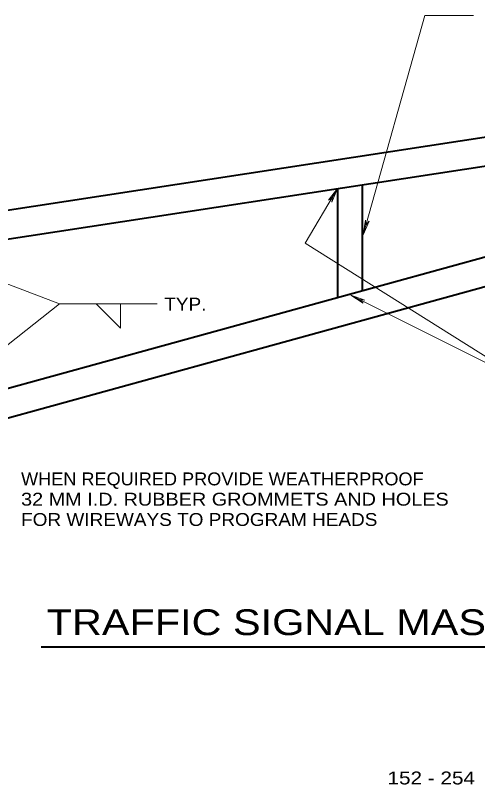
# Model space of a CAD drawing. Extents: x 312583 to 312854, y 144419 to 144597.
# Drawn here: x 312762.98 to 312790.22, y 144520.85 to 144566.2 of the extents above; entities that cross this region are included whole.
import ezdxf

# ---------------------------------------------------------------- set-up
doc = ezdxf.new("R2010")
doc.units = 0
doc.header["$LTSCALE"] = 0.3
doc.layers.add('1', color=7, linetype='Continuous', lineweight=13)

msp = doc.modelspace()

# ---------------------------------------------------------------- linework, layer by layer
at = {"layer": '1'}
for p, q in [((312783.4824, 144553.2632), (312787.101, 144566.2046)), ((312787.101, 144566.2046), (312789.976, 144566.2046)), ((312781.9644, 144556.0002), (312781.4354, 144555.3102)), ((312781.9644, 144556.0002), (312781.6194, 144555.1952)), ((312781.4354, 144555.3102), (312781.6654, 144555.4866)), ((312781.6194, 144555.1952), (312781.6654, 144555.4866)), ((312783.4824, 144553.2632), (312783.6127, 144554.1296)), ((312783.6127, 144554.1296), (312783.6357, 144553.8306)), ((312783.4824, 144553.2632), (312783.8197, 144554.0682)), ((312783.8197, 144554.0682), (312783.6357, 144553.8306)), ((312782.7464, 144549.7136), (312783.4747, 144549.2306)), ((312782.7464, 144549.7136), (312783.5667, 144549.4222)), ((312771.3307, 144549.1999), (312765.573, 144549.1999)), ((312783.4747, 144549.2306), (312783.2754, 144549.4529)), ((312783.5667, 144549.4222), (312783.2754, 144549.4529))]:
    msp.add_line(p, q, dxfattribs=at)
at = {"layer": '1', "lineweight": 40}
for p, q in [((312730.935, 144549.8976), (312834.251, 144565.6909)), ((312730.935, 144548.1956), (312834.504, 144564.0272)), ((312730.935, 144535.5226), (312830.111, 144562.8236)), ((312730.9427, 144533.7822), (312830.5557, 144561.2059)), ((312781.9644, 144556.0002), (312781.9644, 144549.5679)), ((312783.4057, 144556.2149), (312783.4057, 144549.9589)), ((312764.502, 144528.9796), (312823.7493, 144528.9796))]:
    msp.add_line(p, q, dxfattribs=at)
at = {"layer": '1'}
for points in [[(312781.9644, 144556.0002), (312780.063, 144552.7726), (312793.4644, 144544.3469), (312782.7464, 144549.7136)], [(312757.5307, 144542.8366), (312765.573, 144549.1999), (312757.5307, 144552.2589)], [(312767.735, 144549.1999), (312769.1687, 144547.7662), (312769.1687, 144549.1999)]]:
    msp.add_lwpolyline(points, dxfattribs=at)

# ---------------------------------------------------------------- texts
for s, height, width, p in [('TYP.', 0.76, 1.1, (312771.7562, 144548.7993)), ('WHEN REQUIRED PROVIDE WEATHERPROOF', 0.76, 1.05, (312763.319, 144538.4962)), ('32 MM I.D. RUBBER GROMMETS AND HOLES', 0.76, 1.15, (312763.319, 144537.2992)), ('FOR WIREWAYS TO PROGRAM HEADS', 0.76, 1.1, (312763.319, 144536.1022)), ('TRAFFIC SIGNAL MAST ARM FOR TYPE "K" POLES', 1.52, 1.2, (312764.8291, 144529.6655)), ('152 - 254', 0.76, 1.2, (312784.9086, 144520.8628))]:
    msp.add_text(s, height=height, dxfattribs=dict(at, width=width)).set_placement(p)

doc.saveas('drawing.dxf')
